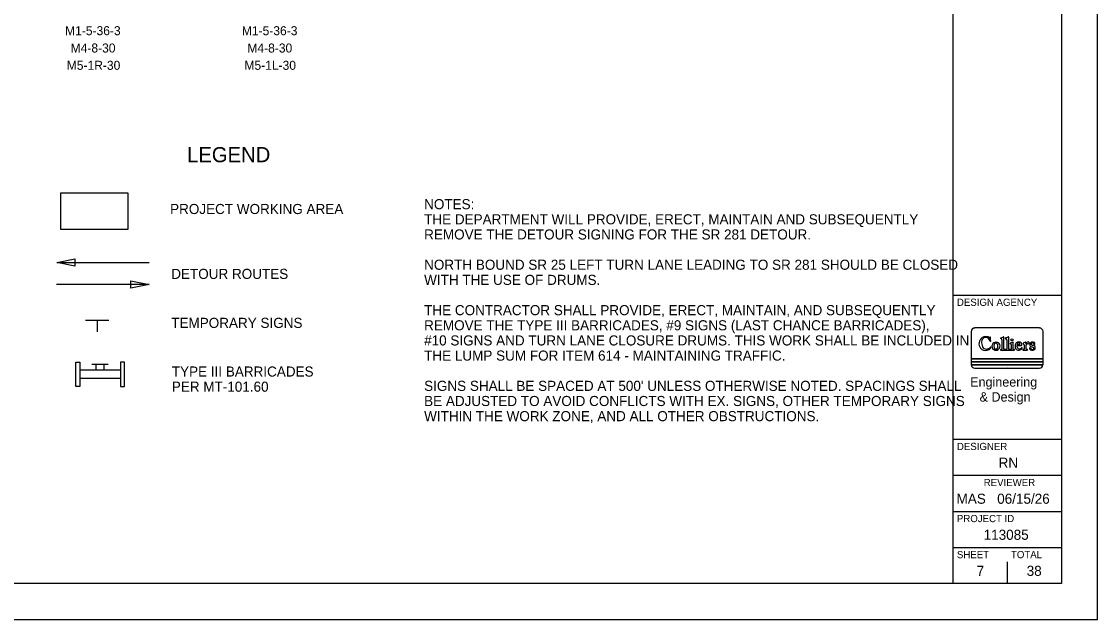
# Model space of a CAD drawing. Extents: x 0 to 680, y 0 to 834.
# Drawn here: x 381.5 to 680, y 0 to 165.9 of the extents above; entities that cross this region are included whole.
import ezdxf

# ---------------------------------------------------------------- set-up
doc = ezdxf.new("R2010")
doc.units = 0
for name, color, linetype in [('MT_P_Cells', 7, 'Continuous'), ('SH_Border', 7, 'Continuous'), ('SH_Cut_Line', 7, 'Continuous'), ('SH_Data', 7, 'Continuous'), ('SH_Text', 7, 'Continuous'), ('SN_P_Text', 7, 'Continuous')]:
    doc.layers.add(name, color=color, linetype=linetype)

msp = doc.modelspace()

# ---------------------------------------------------------------- linework, layer by layer
at = {"layer": 'MT_P_Cells'}
for p, q in [((408.9, 69.12), (397.65, 69.12)), ((401.02, 70.81), (405.52, 70.81)), ((402.15, 69.12), (402.15, 70.81)), ((404.4, 69.12), (404.4, 70.81)), ((408.9, 66.87), (397.65, 66.87)), ((403.27, 67.99), (403.27, 67.99))]:
    msp.add_line(p, q, dxfattribs=at)
for points in [[(396.52, 64.62), (396.52, 71.37), (397.65, 71.37), (397.65, 64.62)], [(410.02, 64.62), (410.02, 71.37), (408.9, 71.37), (408.9, 64.62)]]:
    msp.add_lwpolyline(points, close=True, dxfattribs=at)
at = {"layer": 'SH_Border'}
for p, q in [((640, 10), (640, 430)), ((640, 90), (670, 90)), ((640, 50), (670, 50)), ((640, 40), (670, 40)), ((640, 30), (670, 30)), ((640, 20), (670, 20))]:
    msp.add_line(p, q, dxfattribs=at)
msp.add_lwpolyline([(30, 430), (670, 430), (670, 10), (30, 10)], close=True, dxfattribs=at)
at = {"layer": 'SH_Cut_Line'}
msp.add_lwpolyline([(0, 0), (680, 0), (680, 440), (0, 440)], close=True, dxfattribs=at)
at = {"layer": 'SH_Data'}
for p, q in [((663.89, 80.86), (645.98, 80.86)), ((650.13, 78.27), (650.13, 78.21)), ((653.47, 77.62), (653.47, 75.06)), ((654.02, 75.05), (654.02, 78.32)), ((655.36, 75.02), (655.36, 78.33)), ((650.22, 77.28), (650.26, 77.19)), ((650.35, 75.3), (650.44, 75.39)), ((651.91, 76.91), (651.8, 76.91)), ((653.34, 74.9), (653.15, 74.9)), ((653.15, 74.74), (656.9, 74.74)), ((654.68, 74.89), (654.15, 74.89)), ((654.81, 77.59), (654.81, 75.03)), ((655.99, 74.89), (655.48, 74.89)), ((656.55, 76.93), (655.82, 76.65)), ((656.09, 76.25), (656.09, 75.02)), ((656.64, 74.99), (656.64, 76.86)), ((656.9, 74.89), (656.73, 74.89)), ((657.73, 76.04), (658.93, 76.04)), ((658.38, 76.2), (657.75, 76.2)), ((659.51, 74.89), (659.37, 74.89)), ((659.37, 74.74), (660.53, 74.74)), ((660.01, 76.93), (659.38, 76.62)), ((659.38, 76.5), (659.51, 76.43)), ((659.65, 76.19), (659.65, 75.06)), ((660.15, 76.56), (660.12, 76.87)), ((660.2, 75.05), (660.2, 76.14)), ((660.53, 74.89), (660.34, 74.89)), ((662.19, 76.66), (662.49, 76.33)), ((662.65, 76.4), (662.6, 76.7)), ((644.99, 70.65), (664.89, 70.65)), ((664.89, 70.65), (644.99, 70.65)), ((645.98, 69.71), (663.89, 69.71)), ((655, 70), (655, 70)), ((664.89, 70.71), (664.89, 71.5)), ((655, 10), (655, 16)), ((647.5, 13.5), (647.5, 13.5))]:
    msp.add_line(p, q, dxfattribs=at)
for points in [[(644.99, 79.86), (644.99, 72.35), (664.89, 72.35), (664.89, 79.86)], [(650.41, 77.22), (650.32, 77.72), (650.28, 78.29)], [(664.89, 71.5), (644.99, 71.5), (644.99, 70.71)]]:
    msp.add_lwpolyline(points, dxfattribs=at)
msp.add_lwpolyline([(664.89, 72.35), (644.99, 72.35), (644.99, 71.5), (664.89, 71.5)], close=True, dxfattribs=at)
msp.add_circle((656.3, 77.57), 0.31, dxfattribs=at)
for centre, radius, start, end in [((645.98, 79.86), 0.995, 90, 180), ((663.89, 79.86), 0.995, 0, 90), ((649.11, 76.51), 1.99, 122.7772, 219.4331), ((649.13, 76.97), 1.3, 110.6135, 175.9543), ((648.99, 76.7), 1.77, 54.7696, 122.7772), ((648.99, 77.34), 0.908, 67.8997, 110.6135), ((648.74, 76.71), 1.59, 21.2674, 67.8997), ((650.06, 78.21), 0.0762, 234.7696, 0.2433), ((650.21, 78.27), 0.0784, 10.93, 183.8175), ((653.13, 78.02), 0.0646, 122.5943, 271.3615), ((650.88, 84.43), 6.73, 289.2258, 296.5694), ((653.14, 77.62), 0.331, 0, 91.3615), ((653.93, 78.32), 0.0933, 0.7043, 112.8976), ((654.48, 78.04), 0.0753, 108.5217, 257.147), ((652.82, 83.37), 5.5, 287.2899, 295.7863), ((654.43, 77.59), 0.381, 0, 85.065), ((655.26, 78.32), 0.101, 3.9002, 114.2106), ((648.9, 76.33), 1.71, 219.4331, 285.3506), ((650.52, 76.87), 2.7, 175.9543, 206.5569), ((649.17, 76.19), 1.18, 206.5569, 271.2175), ((649.16, 76.56), 1.55, 271.2175, 317.7042), ((648.8, 76.68), 2.08, 285.3506, 318.3029), ((650.33, 77.23), 0.0854, 213.048, 354.7379), ((650.37, 75.46), 0.0911, 317.5815, 137.7042), ((651.87, 75.8), 1.15, 155.0154, 195.9836), ((651.86, 75.79), 1.14, 195.9836, 247.4134), ((651.83, 75.82), 1.1, 91.4708, 155.0154), ((652.53, 75.81), 1.26, 159.8672, 197.1421), ((652.34, 75.75), 1.05, 197.1421, 229.9048), ((652.26, 75.91), 0.97, 128.4847, 159.8672), ((651.82, 75.69), 1.02, 247.4134, 292.5866), ((651.84, 76.44), 0.286, 51.5153, 128.4847), ((651.86, 75.18), 0.314, 229.9048, 310.0952), ((651.91, 75.82), 1.09, 22.5432, 90), ((651.45, 75.95), 0.914, 8.6045, 51.5153), ((651.45, 75.64), 0.926, 311.5123, 356.3189), ((651.71, 75.95), 1.3, 292.5866, 340.2533), ((650.64, 75.75), 1.74, 354.2931, 11.1311), ((651.98, 75.85), 1.02, 340.2533, 22.5432), ((653.15, 74.82), 0.0824, 90, 270), ((653.34, 75.04), 0.139, 270, 7.6881), ((654.18, 75.05), 0.161, 180, 256.9766), ((654.68, 75.02), 0.13, 270, 3.1556), ((655.49, 75.02), 0.13, 179.2506, 264.6402), ((655.87, 76.58), 0.0797, 126.9098, 263.7558), ((655.84, 76.25), 0.256, 0, 83.7558), ((655.99, 75), 0.106, 270, 12.3402), ((656.57, 76.87), 0.0648, 356.2318, 111.3032), ((656.73, 74.99), 0.097, 180, 266.7746), ((656.9, 74.81), 0.0761, 270, 90), ((658.71, 75.79), 1.57, 158.9201, 196.7689), ((658.08, 75.6), 0.911, 196.7689, 259.4625), ((658.12, 76.02), 0.935, 107.3884, 158.9201), ((657.73, 75.96), 0.0735, 90, 174.8749), ((658.57, 75.89), 0.918, 174.8749, 230.9242), ((658.33, 76.13), 0.665, 120.4846, 167.2691), ((657.75, 76.27), 0.0676, 167.2691, 270), ((658.17, 75.84), 1.11, 72.6116, 107.3884), ((658.12, 75.81), 1.13, 259.4625, 329.9587), ((658.39, 75.67), 0.641, 230.9242, 328.1623), ((658.14, 76.46), 0.287, 42.3189, 120.4846), ((658.01, 76.34), 0.462, 354.1231, 42.3189), ((658.36, 76.31), 0.109, 277.2594, 354.1231), ((658.28, 76.18), 0.762, 357.2625, 72.6116), ((658.93, 76.15), 0.111, 272.7564, 357.2625), ((659.01, 75.29), 0.0907, 329.9587, 148.1623), ((659.37, 74.81), 0.0761, 91.0116, 270), ((659.41, 76.56), 0.068, 121.2415, 241.2505), ((659.37, 76.19), 0.273, 0, 59.7444), ((659.51, 75.03), 0.141, 270, 9.7141), ((660.04, 76.86), 0.075, 6.4513, 116.174), ((660.18, 76.56), 0.0315, 185.3907, 323.4477), ((661.87, 75.3), 2.08, 130.2856, 143.4477), ((660.67, 76.14), 0.47, 141.4263, 180.0327), ((660.36, 75.05), 0.159, 179.3196, 263.9925), ((660.46, 76.3), 0.211, 58.8554, 141.4263), ((660.76, 76.62), 0.358, 49.7144, 130.2856), ((660.53, 74.81), 0.0761, 270, 90), ((660.76, 76.79), 0.359, 238.8554, 310.2856), ((660.83, 76.7), 0.249, 310.2856, 49.7144), ((661.87, 76.24), 0.663, 143.4089, 199.3264), ((661.31, 75.35), 0.0971, 20.4198, 193.2731), ((658.96, 74.8), 2.31, 4.8826, 13.2731), ((661.74, 76.2), 0.525, 199.3264, 242.7351), ((661.54, 75.02), 0.281, 184.8826, 242.2064), ((661.87, 76.24), 0.668, 105.6066, 143.4089), ((662.36, 75.75), 1.03, 200.4198, 231.7135), ((661.87, 75.63), 0.972, 242.2064, 319.0024), ((662.82, 78.3), 2.89, 242.7351, 255.1442), ((661.86, 76.44), 0.265, 123.6114, 236.3886), ((661.99, 75.81), 1.12, 61.5074, 105.6066), ((661.97, 76.26), 0.477, 78.1441, 123.6114), ((662.23, 76.99), 0.936, 236.3886, 262.0524), ((661.95, 75.23), 0.37, 231.7135, 325.4966), ((662.02, 76.5), 0.23, 42.5173, 78.1441), ((662, 75.2), 0.32, 325.4966, 75.1442), ((661.99, 75.26), 0.815, 40.9976, 82.0524), ((662.56, 76.38), 0.0867, 219.7222, 9.1323), ((662.45, 76.65), 0.159, 16.8946, 61.5074), ((662.14, 75.39), 0.611, 319.0024, 40.9976), ((645.98, 70.71), 0.995, 180, 183.1495), ((645.98, 70.71), 0.995, 183.1495, 270), ((663.89, 70.71), 0.995, 270, 356.8505), ((663.89, 70.71), 0.995, 356.8505, 0)]:
    msp.add_arc(centre, radius, start, end, dxfattribs=at)
at = {"layer": 'SH_Text'}
for p, q in [((391.25, 99.03), (416.87, 99.03)), ((416.85, 92.95), (391.22, 92.95)), ((399.26, 82.99), (405.66, 82.99)), ((402.46, 82.99), (402.46, 79.79))]:
    msp.add_line(p, q, dxfattribs=at)
for points in [[(392.43, 118.35), (411.01, 118.35), (411.01, 108.21), (392.43, 108.21)], [(396.29, 98.02), (391.25, 99.03), (396.29, 100.04)], [(411.81, 93.96), (416.85, 92.95), (411.81, 91.95)]]:
    msp.add_lwpolyline(points, close=True, dxfattribs=at)

# ---------------------------------------------------------------- texts
at = {"layer": 'SH_Data'}
for s, height, p in [('DESIGN AGENCY', 2, (641, 87)), ('Engineering', 2.6051, (644.68, 64.58)), ('& Design', 2.605, (647.3, 60.44)), ('DESIGNER', 2, (641, 47)), ('RN', 2.8, (652.56, 42.1)), ('REVIEWER', 2, (648.44, 37)), ('MAS', 2.8, (640.9, 32.1)), ('06/15/26', 2.8, (652.18, 32.1)), ('PROJECT ID', 2, (641, 27)), ('113085', 2.8, (648.42, 22.1)), ('SHEET', 2, (641, 17)), ('TOTAL', 2, (656, 17)), ('38', 2.8, (660.36, 12.1)), ('7', 2.8, (646.48, 12.1))]:
    msp.add_text(s, height=height, dxfattribs=at).set_placement(p)
at = {"layer": 'SH_Text'}
for s, height, p in [('LEGEND', 4.2, (427.41, 126.85)), ('NOTES: ', 2.8, (493.18, 113.81)), ('PROJECT WORKING AREA', 2.8, (422.7, 112.47)), ('THE DEPARTMENT WILL PROVIDE, ERECT, MAINTAIN AND SUBSEQUENTLY', 2.8, (493.18, 109.61)), ('REMOVE THE DETOUR SIGNING FOR THE SR 281 DETOUR.', 2.8, (493.18, 105.41)), ('NORTH BOUND SR 25 LEFT TURN LANE LEADING TO SR 281 SHOULD BE CLOSED ', 2.8, (493.18, 97.01)), ('DETOUR ROUTES', 2.8, (423.02, 94.47)), ('WITH THE USE OF DRUMS.', 2.8, (493.18, 92.81)), ('THE CONTRACTOR SHALL PROVIDE, ERECT, MAINTAIN, AND SUBSEQUENTLY', 2.8, (493.18, 84.41)), ('TEMPORARY SIGNS', 2.8, (423.02, 80.88)), ('REMOVE THE TYPE III BARRICADES, #9 SIGNS (LAST CHANCE BARRICADES), ', 2.8, (493.18, 80.21)), ('#10 SIGNS AND TURN LANE CLOSURE DRUMS. THIS WORK SHALL BE INCLUDED IN', 2.8, (493.18, 76.01)), ('THE LUMP SUM FOR ITEM 614 - MAINTAINING TRAFFIC.', 2.8, (493.18, 71.81)), ('TYPE III BARRICADES', 2.8, (423.18, 67.38)), ('PER MT-101.60', 2.8, (423.18, 63.18)), ("SIGNS SHALL BE SPACED AT 500' UNLESS OTHERWISE NOTED. SPACINGS SHALL", 2.8, (493.18, 63.41)), ('BE ADJUSTED TO AVOID CONFLICTS WITH EX. SIGNS, OTHER TEMPORARY SIGNS', 2.8, (493.18, 59.21)), ('WITHIN THE WORK ZONE, AND ALL OTHER OBSTRUCTIONS.', 2.8, (493.18, 55.01))]:
    msp.add_text(s, height=height, dxfattribs=at).set_placement(p)
at = {"layer": 'SN_P_Text'}
for s, p in [('M1-5-36-3', (393.56, 162.08)), ('M1-5-36-3', (442.61, 162.08)), ('M4-8-30', (395.1, 157.28)), ('M4-8-30', (444.14, 157.28)), ('M5-1R-30', (394.03, 152.48)), ('M5-1L-30', (443.32, 152.48))]:
    msp.add_text(s, height=2.5, dxfattribs=at).set_placement(p)

doc.saveas('drawing.dxf')
